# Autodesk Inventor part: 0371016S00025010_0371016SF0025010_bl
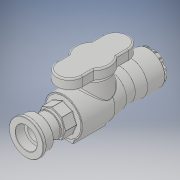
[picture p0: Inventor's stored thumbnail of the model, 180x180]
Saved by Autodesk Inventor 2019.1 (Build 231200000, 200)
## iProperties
Created: 2022-04
Part Number: 0371016S00025010_0371016SF0025010_bl
Material: Generic
Description: PA Ball Valve Series 1 25mm x Free Nut Female 1''
Document SubType Name: Modeling
Designer: Lenora
Density: 1 g/cm^3
Appearance: Default
Author: Lenora
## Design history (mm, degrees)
derived "0371016.ipt"
feature "Solid1::0371016.ipt" dims "ScaleForDerivedMember" = 10
tag "TaggingFeature1"
body "Solid1"
other parameters: "d" = 25 [user parameter], "DN" = 25 [user parameter], "A1" = 27 [user parameter], "A2" = 54 [user parameter], "H_" = 179 [user parameter], "E_" = 53 [user parameter], "E1" = 47 [user parameter], "B" = 36 [user parameter], "l2" = 19 [user parameter], "G" = 30.291 [user parameter], "E2" = 48 [user parameter], "d0" = 179 [user parameter], "d16" = 85.92 [user parameter], "d19" = 1 [user parameter], "d20" = 44.75 [user parameter], "d22" = 85 deg [user parameter], "d25" = 1 [user parameter], "d34" = 32.22 [user parameter], "d35" = 17.9 [user parameter], "d37" = 0 [user parameter], "d39" = 360 deg [user parameter], "d43" = 27 [user parameter], "d45" = 70 deg [user parameter], "d46" = 70 deg [user parameter], "d48" = 0 [user parameter], "d57" = 2 [user parameter], "d60" = 25 [user parameter], "d63" = 53 [user parameter], "d71" = 8.95 [user parameter], "d72" = 13.425 [user parameter], "d73" = 32.22 [user parameter], "d76" = 54 [user parameter], "d77" = 16.2 [user parameter], "d78" = 48.33 [user parameter], "d79" = 22.375 [user parameter], "d80" = 100 deg [user parameter], "d81" = 15.215 [user parameter], "d83" = 22.95 [user parameter], "d84" = 13.425 [user parameter], "d85" = 26.5 [user parameter], "d90" = 0 [user parameter], "d91" = 7.95 [user parameter], "d92" = 45 deg [user parameter], "d93" = 4.24 [user parameter], "d94" = 1.696 [user parameter], "d95" = 2.12 [user parameter], "d96" = 2.12 [user parameter], "d97" = 2.12 [user parameter], "d98" = 2.12 [user parameter], "d111" = 0.5 [user parameter], "d112" = 2 [user parameter], "d114" = 7.42 [user parameter], "d115" = 0 [user parameter], "d117" = 360 deg [user parameter], "d119" = 42.93 [user parameter], "d120" = 47 [user parameter], "d121" = 25 [user parameter], "d122" = 1 [user parameter], "d123" = 89 deg [user parameter], "d124" = 80 deg [user parameter], "d125" = 36 [user parameter], "d127" = 15.2 [user parameter], "d132" = 49.29 [user parameter], "d134" = 0 [user parameter], "d140" = 30.291 [user parameter], "d141" = 21.2037 [user parameter], "d142" = 12.53 [user parameter], "d144" = 43.2 [user parameter], "d145" = 12.53 [user parameter], "d146" = 4.475 [user parameter], "d147" = 33.3201 [user parameter], "d148" = 17.9 [user parameter], "d149" = 35.8 [user parameter], "d150" = 32.22 [user parameter], "d152" = 48 [user parameter], "d153" = 19 [user parameter], "d155" = 0.5 [user parameter]
